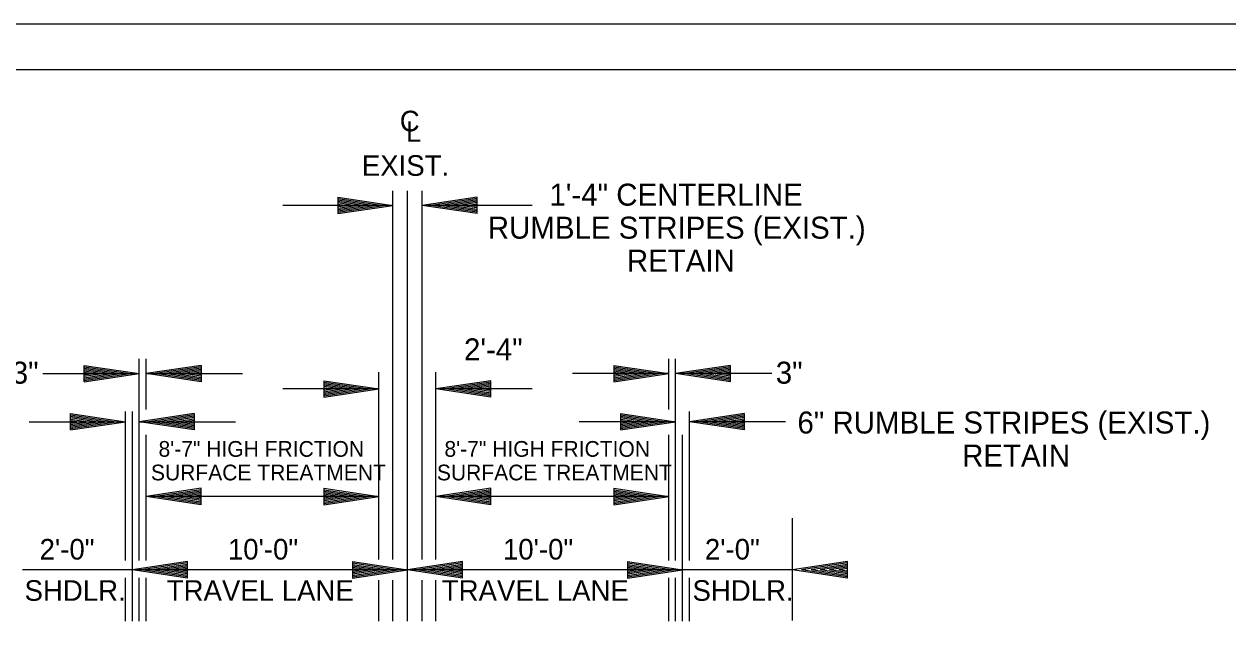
# Model space of a CAD drawing. Extents: x 34757 to 38214, y 51436 to 59430.
# Drawn here: x 35398 to 36054, y 54141 to 54470 of the extents above; entities that cross this region are included whole.
import ezdxf

# ---------------------------------------------------------------- set-up
doc = ezdxf.new("R2010")
doc.units = 0
for name, color, linetype in [('Default', 7, 'Continuous'), ('DSN_DRFT_Junk-No-Plot', 7, 'Continuous'), ('SHET_Border-Lines', 7, 'Continuous')]:
    doc.layers.add(name, color=color, linetype=linetype)

msp = doc.modelspace()

# ---------------------------------------------------------------- linework, layer by layer
at = {"layer": 'Default'}
for p, q in [((35568.64, 54375.22), (35598.64, 54370.72)), ((35568.64, 54375.22), (35568.64, 54366.22)), ((35598.64, 54287.77), (35598.64, 54378.66)), ((35606.64, 54287.77), (35606.64, 54378.66)), ((35614.64, 54287.77), (35614.64, 54378.66)), ((35644.64, 54375.22), (35614.64, 54370.72)), ((35644.64, 54366.22), (35644.64, 54375.22)), ((35598.64, 54370.72), (35538.64, 54370.72)), ((35568.64, 54374.47), (35593.63, 54370.72)), ((35568.64, 54373.71), (35588.47, 54370.72)), ((35568.64, 54372.96), (35583.47, 54370.72)), ((35568.64, 54372.18), (35578.39, 54370.72)), ((35568.64, 54371.43), (35573.38, 54370.72)), ((35568.64, 54366.22), (35598.64, 54370.72)), ((35568.64, 54369.25), (35578.39, 54370.72)), ((35568.64, 54367.74), (35588.47, 54370.72)), ((35568.64, 54366.97), (35593.63, 54370.72)), ((35568.64, 54368.49), (35583.47, 54370.72)), ((35568.64, 54370.02), (35573.38, 54370.72)), ((35644.64, 54366.22), (35614.64, 54370.72)), ((35674.64, 54370.72), (35614.64, 54370.72)), ((35644.64, 54374.47), (35619.65, 54370.72)), ((35644.64, 54366.97), (35619.65, 54370.72)), ((35644.64, 54373.71), (35624.81, 54370.72)), ((35644.64, 54367.74), (35624.81, 54370.72)), ((35644.64, 54372.96), (35629.8, 54370.72)), ((35644.64, 54368.49), (35629.8, 54370.72)), ((35644.64, 54372.19), (35634.89, 54370.72)), ((35644.64, 54369.27), (35634.89, 54370.72)), ((35644.64, 54371.43), (35639.9, 54370.72)), ((35644.64, 54370.02), (35639.9, 54370.72)), ((35430.39, 54283.42), (35460.39, 54278.92)), ((35430.39, 54274.42), (35430.39, 54283.42)), ((35460.39, 54176.99), (35460.39, 54286.95)), ((35464.14, 54259.28), (35464.14, 54286.95)), ((35494.14, 54283.42), (35464.14, 54278.92)), ((35494.14, 54283.42), (35494.14, 54274.42)), ((35598.64, 54177.49), (35598.64, 54287.77)), ((35606.64, 54143.87), (35606.64, 54287.77)), ((35614.64, 54177.49), (35614.64, 54287.77)), ((35719.14, 54283.42), (35749.14, 54278.92)), ((35719.14, 54283.42), (35719.14, 54274.42)), ((35749.14, 54259.28), (35749.14, 54286.95)), ((35752.89, 54176.99), (35752.89, 54286.95)), ((35782.89, 54283.42), (35752.89, 54278.92)), ((35782.89, 54274.42), (35782.89, 54283.42)), ((35407.89, 54278.92), (35460.39, 54278.92)), ((35430.39, 54282.67), (35455.38, 54278.92)), ((35430.39, 54281.91), (35450.22, 54278.92)), ((35430.39, 54281.16), (35445.22, 54278.92)), ((35430.39, 54280.39), (35440.14, 54278.92)), ((35430.39, 54279.63), (35435.13, 54278.92)), ((35430.39, 54274.42), (35460.39, 54278.92)), ((35430.39, 54277.47), (35440.14, 54278.92)), ((35430.39, 54275.94), (35450.22, 54278.92)), ((35430.39, 54275.17), (35455.38, 54278.92)), ((35430.39, 54276.69), (35445.22, 54278.92)), ((35430.39, 54278.22), (35435.13, 54278.92)), ((35494.14, 54274.42), (35464.14, 54278.92)), ((35464.14, 54278.92), (35516.64, 54278.92)), ((35494.14, 54282.67), (35469.15, 54278.92)), ((35494.14, 54275.17), (35469.15, 54278.92)), ((35494.14, 54281.91), (35474.31, 54278.92)), ((35494.14, 54275.94), (35474.31, 54278.92)), ((35494.14, 54281.16), (35479.3, 54278.92)), ((35494.14, 54276.69), (35479.3, 54278.92)), ((35494.14, 54280.38), (35484.39, 54278.92)), ((35494.14, 54277.45), (35484.39, 54278.92)), ((35494.14, 54279.63), (35489.4, 54278.92)), ((35494.14, 54278.22), (35489.4, 54278.92)), ((35591.14, 54177.49), (35591.14, 54279.8)), ((35622.14, 54177.49), (35622.14, 54279.8)), ((35749.14, 54278.92), (35696.64, 54278.92)), ((35719.14, 54282.67), (35744.13, 54278.92)), ((35719.14, 54281.91), (35738.97, 54278.92)), ((35719.14, 54281.16), (35733.97, 54278.92)), ((35719.14, 54280.38), (35728.89, 54278.92)), ((35719.14, 54279.63), (35723.88, 54278.92)), ((35719.14, 54274.42), (35749.14, 54278.92)), ((35719.14, 54277.45), (35728.89, 54278.92)), ((35719.14, 54275.94), (35738.97, 54278.92)), ((35719.14, 54275.17), (35744.13, 54278.92)), ((35719.14, 54276.69), (35733.97, 54278.92)), ((35719.14, 54278.22), (35723.88, 54278.92)), ((35805.39, 54278.92), (35752.89, 54278.92)), ((35782.89, 54274.42), (35752.89, 54278.92)), ((35782.89, 54282.67), (35757.9, 54278.92)), ((35782.89, 54275.17), (35757.9, 54278.92)), ((35782.89, 54281.91), (35763.06, 54278.92)), ((35782.89, 54275.94), (35763.06, 54278.92)), ((35782.89, 54281.16), (35768.05, 54278.92)), ((35782.89, 54276.69), (35768.05, 54278.92)), ((35782.89, 54280.39), (35773.14, 54278.92)), ((35782.89, 54277.47), (35773.14, 54278.92)), ((35782.89, 54279.63), (35778.15, 54278.92)), ((35782.89, 54278.22), (35778.15, 54278.92)), ((35591.14, 54270.53), (35538.64, 54270.53)), ((35561.14, 54275.03), (35591.14, 54270.53)), ((35561.14, 54275.03), (35561.14, 54266.03)), ((35561.14, 54274.28), (35586.13, 54270.53)), ((35561.14, 54273.52), (35580.97, 54270.53)), ((35561.14, 54272.77), (35575.97, 54270.53)), ((35561.14, 54271.99), (35570.89, 54270.53)), ((35561.14, 54271.24), (35565.88, 54270.53)), ((35561.14, 54266.03), (35591.14, 54270.53)), ((35561.14, 54269.06), (35570.89, 54270.53)), ((35561.14, 54267.55), (35580.97, 54270.53)), ((35561.14, 54266.78), (35586.13, 54270.53)), ((35561.14, 54268.3), (35575.97, 54270.53)), ((35561.14, 54269.83), (35565.88, 54270.53)), ((35652.14, 54275.03), (35622.14, 54270.53)), ((35674.64, 54270.53), (35622.14, 54270.53)), ((35652.14, 54266.03), (35622.14, 54270.53)), ((35652.14, 54274.28), (35627.15, 54270.53)), ((35652.14, 54266.78), (35627.15, 54270.53)), ((35652.14, 54273.52), (35632.31, 54270.53)), ((35652.14, 54267.55), (35632.31, 54270.53)), ((35652.14, 54272.77), (35637.3, 54270.53)), ((35652.14, 54268.3), (35637.3, 54270.53)), ((35652.14, 54272), (35642.39, 54270.53)), ((35652.14, 54269.08), (35642.39, 54270.53)), ((35652.14, 54271.24), (35647.4, 54270.53)), ((35652.14, 54269.83), (35647.4, 54270.53)), ((35652.14, 54266.03), (35652.14, 54275.03)), ((35422.89, 54257.18), (35452.89, 54252.68)), ((35422.89, 54248.18), (35422.89, 54257.18)), ((35452.89, 54176.99), (35452.89, 54258.25)), ((35456.64, 54143.87), (35456.64, 54258.25)), ((35490.39, 54257.18), (35460.39, 54252.68)), ((35490.39, 54257.18), (35490.39, 54248.18)), ((35722.89, 54257.18), (35752.89, 54252.68)), ((35722.89, 54257.18), (35722.89, 54248.18)), ((35760.39, 54176.99), (35760.39, 54258.25)), ((35790.39, 54257.18), (35760.39, 54252.68)), ((35790.39, 54248.18), (35790.39, 54257.18)), ((35400.39, 54252.68), (35452.89, 54252.68)), ((35422.89, 54256.43), (35447.88, 54252.68)), ((35422.89, 54255.66), (35442.72, 54252.68)), ((35422.89, 54254.91), (35437.72, 54252.68)), ((35422.89, 54254.15), (35432.64, 54252.68)), ((35422.89, 54253.38), (35427.63, 54252.68)), ((35422.89, 54248.18), (35452.89, 54252.68)), ((35422.89, 54251.22), (35432.64, 54252.68)), ((35422.89, 54249.69), (35442.72, 54252.68)), ((35422.89, 54248.93), (35447.88, 54252.68)), ((35422.89, 54250.44), (35437.72, 54252.68)), ((35422.89, 54251.97), (35427.63, 54252.68)), ((35490.39, 54248.18), (35460.39, 54252.68)), ((35460.39, 54252.68), (35512.89, 54252.68)), ((35490.39, 54256.43), (35465.4, 54252.68)), ((35490.39, 54248.93), (35465.4, 54252.68)), ((35490.39, 54255.66), (35470.56, 54252.68)), ((35490.39, 54249.69), (35470.56, 54252.68)), ((35490.39, 54254.91), (35475.55, 54252.68)), ((35490.39, 54250.44), (35475.55, 54252.68)), ((35490.39, 54254.13), (35480.64, 54252.68)), ((35490.39, 54251.21), (35480.64, 54252.68)), ((35490.39, 54253.38), (35485.65, 54252.68)), ((35490.39, 54251.97), (35485.65, 54252.68)), ((35752.89, 54252.68), (35700.39, 54252.68)), ((35722.89, 54256.43), (35747.88, 54252.68)), ((35722.89, 54255.66), (35742.72, 54252.68)), ((35722.89, 54254.91), (35737.72, 54252.68)), ((35722.89, 54254.13), (35732.64, 54252.68)), ((35722.89, 54253.38), (35727.63, 54252.68)), ((35722.89, 54248.18), (35752.89, 54252.68)), ((35722.89, 54251.21), (35732.64, 54252.68)), ((35722.89, 54249.69), (35742.72, 54252.68)), ((35722.89, 54248.93), (35747.88, 54252.68)), ((35722.89, 54250.44), (35737.72, 54252.68)), ((35722.89, 54251.97), (35727.63, 54252.68)), ((35812.89, 54252.68), (35760.39, 54252.68)), ((35790.39, 54248.18), (35760.39, 54252.68)), ((35790.39, 54256.43), (35765.4, 54252.68)), ((35790.39, 54248.93), (35765.4, 54252.68)), ((35790.39, 54255.66), (35770.56, 54252.68)), ((35790.39, 54249.69), (35770.56, 54252.68)), ((35790.39, 54254.91), (35775.55, 54252.68)), ((35790.39, 54250.44), (35775.55, 54252.68)), ((35790.39, 54254.15), (35780.64, 54252.68)), ((35790.39, 54251.22), (35780.64, 54252.68)), ((35790.39, 54253.38), (35785.65, 54252.68)), ((35790.39, 54251.97), (35785.65, 54252.68)), ((35456.64, 54143.87), (35456.64, 54245.48)), ((35464.14, 54176.99), (35464.14, 54245.48)), ((35749.14, 54176.99), (35749.14, 54245.48)), ((35756.64, 54143.87), (35756.64, 54245.48)), ((35494.14, 54216.35), (35464.14, 54211.85)), ((35591.14, 54211.85), (35464.14, 54211.85)), ((35494.14, 54207.35), (35464.14, 54211.85)), ((35494.14, 54215.6), (35469.15, 54211.85)), ((35494.14, 54208.1), (35469.15, 54211.85)), ((35494.14, 54214.83), (35474.31, 54211.85)), ((35494.14, 54208.86), (35474.31, 54211.85)), ((35494.14, 54214.08), (35479.3, 54211.85)), ((35494.14, 54209.61), (35479.3, 54211.85)), ((35494.14, 54213.32), (35484.39, 54211.85)), ((35494.14, 54210.39), (35484.39, 54211.85)), ((35494.14, 54212.55), (35489.4, 54211.85)), ((35494.14, 54211.14), (35489.4, 54211.85)), ((35494.14, 54207.35), (35494.14, 54216.35)), ((35561.14, 54216.35), (35591.14, 54211.85)), ((35561.14, 54216.35), (35561.14, 54207.35)), ((35561.14, 54215.6), (35586.13, 54211.85)), ((35561.14, 54214.83), (35580.97, 54211.85)), ((35561.14, 54214.08), (35575.97, 54211.85)), ((35561.14, 54213.3), (35570.89, 54211.85)), ((35561.14, 54212.55), (35565.88, 54211.85)), ((35561.14, 54207.35), (35591.14, 54211.85)), ((35561.14, 54210.38), (35570.89, 54211.85)), ((35561.14, 54208.86), (35580.97, 54211.85)), ((35561.14, 54208.1), (35586.13, 54211.85)), ((35561.14, 54209.61), (35575.97, 54211.85)), ((35561.14, 54211.14), (35565.88, 54211.85)), ((35652.14, 54216.35), (35622.14, 54211.85)), ((35749.14, 54211.85), (35622.14, 54211.85)), ((35652.14, 54207.35), (35622.14, 54211.85)), ((35652.14, 54215.6), (35627.15, 54211.85)), ((35652.14, 54208.1), (35627.15, 54211.85)), ((35652.14, 54214.83), (35632.31, 54211.85)), ((35652.14, 54208.86), (35632.31, 54211.85)), ((35652.14, 54214.08), (35637.3, 54211.85)), ((35652.14, 54209.61), (35637.3, 54211.85)), ((35652.14, 54213.32), (35642.39, 54211.85)), ((35652.14, 54210.39), (35642.39, 54211.85)), ((35652.14, 54212.55), (35647.4, 54211.85)), ((35652.14, 54211.14), (35647.4, 54211.85)), ((35652.14, 54207.35), (35652.14, 54216.35)), ((35719.14, 54216.35), (35749.14, 54211.85)), ((35719.14, 54216.35), (35719.14, 54207.35)), ((35719.14, 54215.6), (35744.13, 54211.85)), ((35719.14, 54214.83), (35738.97, 54211.85)), ((35719.14, 54214.08), (35733.97, 54211.85)), ((35719.14, 54213.3), (35728.89, 54211.85)), ((35719.14, 54212.55), (35723.88, 54211.85)), ((35719.14, 54207.35), (35749.14, 54211.85)), ((35719.14, 54210.38), (35728.89, 54211.85)), ((35719.14, 54208.86), (35738.97, 54211.85)), ((35719.14, 54208.1), (35744.13, 54211.85)), ((35719.14, 54209.61), (35733.97, 54211.85)), ((35719.14, 54211.14), (35723.88, 54211.85)), ((35816.64, 54144.17), (35816.64, 54200.14)), ((35456.64, 54171.86), (35396.64, 54171.86)), ((35486.64, 54176.36), (35456.64, 54171.86)), ((35606.64, 54171.86), (35456.64, 54171.86)), ((35486.64, 54167.36), (35456.64, 54171.86)), ((35486.64, 54175.61), (35461.65, 54171.86)), ((35486.64, 54168.11), (35461.65, 54171.86)), ((35486.64, 54174.84), (35466.81, 54171.86)), ((35486.64, 54168.87), (35466.81, 54171.86)), ((35486.64, 54174.09), (35471.8, 54171.86)), ((35486.64, 54169.62), (35471.8, 54171.86)), ((35486.64, 54173.33), (35476.89, 54171.86)), ((35486.64, 54170.4), (35476.89, 54171.86)), ((35486.64, 54172.56), (35481.9, 54171.86)), ((35486.64, 54171.15), (35481.9, 54171.86)), ((35486.64, 54167.36), (35486.64, 54176.36)), ((35576.64, 54176.36), (35606.64, 54171.86)), ((35576.64, 54176.36), (35576.64, 54167.36)), ((35576.64, 54175.61), (35601.63, 54171.86)), ((35576.64, 54174.84), (35596.47, 54171.86)), ((35576.64, 54174.09), (35591.47, 54171.86)), ((35576.64, 54173.31), (35586.39, 54171.86)), ((35576.64, 54172.56), (35581.38, 54171.86)), ((35576.64, 54167.36), (35606.64, 54171.86)), ((35576.64, 54170.39), (35586.39, 54171.86)), ((35576.64, 54168.87), (35596.47, 54171.86)), ((35576.64, 54168.11), (35601.63, 54171.86)), ((35576.64, 54169.62), (35591.47, 54171.86)), ((35576.64, 54171.15), (35581.38, 54171.86)), ((35636.64, 54176.36), (35606.64, 54171.86)), ((35756.64, 54171.86), (35606.64, 54171.86)), ((35636.64, 54167.36), (35606.64, 54171.86)), ((35636.64, 54175.61), (35611.65, 54171.86)), ((35636.64, 54168.11), (35611.65, 54171.86)), ((35636.64, 54174.84), (35616.81, 54171.86)), ((35636.64, 54168.87), (35616.81, 54171.86)), ((35636.64, 54174.09), (35621.8, 54171.86)), ((35636.64, 54169.62), (35621.8, 54171.86)), ((35636.64, 54173.33), (35626.89, 54171.86)), ((35636.64, 54170.4), (35626.89, 54171.86)), ((35636.64, 54172.56), (35631.9, 54171.86)), ((35636.64, 54171.15), (35631.9, 54171.86)), ((35636.64, 54167.36), (35636.64, 54176.36)), ((35726.64, 54176.36), (35756.64, 54171.86)), ((35726.64, 54176.36), (35726.64, 54167.36)), ((35726.64, 54175.61), (35751.63, 54171.86)), ((35726.64, 54174.84), (35746.47, 54171.86)), ((35726.64, 54174.09), (35741.47, 54171.86)), ((35726.64, 54173.31), (35736.39, 54171.86)), ((35726.64, 54172.56), (35731.38, 54171.86)), ((35726.64, 54167.36), (35756.64, 54171.86)), ((35726.64, 54170.39), (35736.39, 54171.86)), ((35726.64, 54168.87), (35746.47, 54171.86)), ((35726.64, 54168.11), (35751.63, 54171.86)), ((35726.64, 54169.62), (35741.47, 54171.86)), ((35726.64, 54171.15), (35731.38, 54171.86)), ((35816.64, 54171.86), (35756.64, 54171.86)), ((35846.64, 54176.36), (35816.64, 54171.86)), ((35846.64, 54167.36), (35816.64, 54171.86)), ((35846.64, 54175.61), (35821.65, 54171.86)), ((35846.64, 54168.11), (35821.65, 54171.86)), ((35846.64, 54174.84), (35826.81, 54171.86)), ((35846.64, 54168.87), (35826.81, 54171.86)), ((35846.64, 54174.09), (35831.8, 54171.86)), ((35846.64, 54169.62), (35831.8, 54171.86)), ((35846.64, 54173.33), (35836.89, 54171.86)), ((35846.64, 54170.4), (35836.89, 54171.86)), ((35846.64, 54172.56), (35841.9, 54171.86)), ((35846.64, 54171.15), (35841.9, 54171.86)), ((35846.64, 54167.36), (35846.64, 54176.36)), ((35452.89, 54143.87), (35452.89, 54167.51)), ((35460.39, 54143.87), (35460.39, 54167.51)), ((35464.14, 54143.87), (35464.14, 54167.51)), ((35591.14, 54143.87), (35591.14, 54166.23)), ((35598.64, 54143.87), (35598.64, 54166.23)), ((35614.64, 54143.87), (35614.64, 54166.23)), ((35622.14, 54143.87), (35622.14, 54166.23)), ((35749.14, 54143.87), (35749.14, 54167.51)), ((35752.89, 54143.87), (35752.89, 54167.51)), ((35760.39, 54143.87), (35760.39, 54167.51))]:
    msp.add_line(p, q, dxfattribs=at)
msp.add_lwpolyline([(34756.64, 54469.61), (34756.64, 53369.61), (36456.64, 53369.61), (36456.64, 54469.61)], close=True, dxfattribs=at)
at = {"layer": 'DSN_DRFT_Junk-No-Plot'}
msp.add_lwpolyline([(34756.64, 54469.61), (34756.64, 53369.61), (36456.64, 53369.61), (36456.64, 54469.61)], close=True, dxfattribs=at)
at = {"layer": 'SHET_Border-Lines'}
for points in [[(34756.64, 53369.61), (36456.64, 53369.61), (36456.64, 54469.61), (34756.64, 54469.61)], [(34781.64, 53394.61), (36431.64, 53394.61), (36431.64, 54444.61), (34781.64, 54444.61)]]:
    msp.add_lwpolyline(points, close=True, dxfattribs=at)

# ---------------------------------------------------------------- texts
at = {"layer": 'Default'}
for s, height, p in [('C', 11.24, (35602.47, 54411.09)), ('L', 11.24, (35605.85, 54405.37)), ('EXIST.', 11.239, (35581.79, 54386.82)), ('1\'-4" CENTERLINE ', 12.0068, (35684.09, 54370.54)), ('RUMBLE STRIPES (EXIST.) ', 12.0068, (35650.48, 54352.53)), ('RETAIN', 12.007, (35726.34, 54334.52)), ('2\'-4"', 12.007, (35637.51, 54286.12)), ('3"', 12.007, (35390.86, 54273.43)), ('3"', 12.007, (35807.53, 54273.43)), ('6" RUMBLE STRIPES (EXIST.) ', 12.0068, (35819.35, 54246.23)), ('8\'-7" HIGH FRICTION', 8.5807, (35470.9, 54233.55)), ('8\'-7" HIGH FRICTION', 8.5807, (35626.84, 54233.55)), ('RETAIN', 12.007, (35909.16, 54228.22)), ('SURFACE TREATMENT', 8.5807, (35466.76, 54220.68)), ('SURFACE TREATMENT', 8.5807, (35622.71, 54220.68)), ('2\'-0"', 11.25, (35406.04, 54177.48)), ('10\'-0"', 11.25, (35508.74, 54177.48)), ('10\'-0"', 11.25, (35658.74, 54177.48)), ('2\'-0"', 11.25, (35768.87, 54177.48)), ('SHDLR.', 11.25, (35397.83, 54154.98)), ('TRAVEL LANE', 11.25, (35475.39, 54154.98)), ('TRAVEL LANE', 11.25, (35625.39, 54154.98)), ('SHDLR.', 11.25, (35762.1, 54154.98))]:
    msp.add_text(s, height=height, dxfattribs=at).set_placement(p)

doc.saveas('drawing.dxf')
